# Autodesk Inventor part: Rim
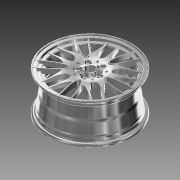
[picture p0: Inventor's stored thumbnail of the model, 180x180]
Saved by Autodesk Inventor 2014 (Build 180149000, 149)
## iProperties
Shininess: 64.0
Length Units: 11269
Angle Units: 11279
Time Units: 11290
Mass Units: 11283
Length Display Precision: 3
Angle Display Precision: 2
Compacted: True
Part Number: Rim
Document SubType Name: Modeling
Created: 2003-06
Manufacturer: Standard
Standards Organization: Custom
Density: 2.71 g/cm^3
Material: Aluminum-6061
Mass: 9934.83 g
Surface Area: 9000.12 cm^2
Volume: 3665.99 cm^3
Appearance: Chrome - Polished
Density: 0.0
Volumn: 0.0
Area: 0.0
PropertySet Name: Model Information
Control State: 0
Master: False
Checked Out: False
Author: Autodesk, Inc.
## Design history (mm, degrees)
workplane "Work Plane4"
workplane "Work Plane1"
sketch "Spoke Side"
  geometry: L1 (0, -11162.344)-(0, 13420.953) reference; L2 (-1298.767, 0)-(7792.602, 0) reference; L3 (0, 55)-(10.286, 55); L4 (205.698, 37.987)-(254.302, 42.013); L5 (37.4, 37.385)-(62.6, 42.615); L6 (0, 0)-(60, 0); L7 (60, 0)-(60, 5); L8 (60, 5)-(65.959, 10); L9 (62.17, 6.821)-(69.748, 13.179); L10 (222.425, 21.138)-(237.575, 18.862); L11 (230, 40)-(230, 20); L12 (0, 55)-(0, 0); A1 r 209.241 centre (212.724, 248.526) between (210.568, 39.297) and (249.283, 42.504); A2 r 109.305 centre (27.793, 147.025) between (39.866, 38.389) and (59.938, 42.554); A3 r 90.833 centre (0, -35.833) between (50, 40) and (0, 55); A4 r 10000 centre (6493.835, -7650.444) between (68.99, 12.543) and (68.985, 12.55); A5 r 10000 centre (1715.468, 9909.054) between (223.941, 20.912) and (236.06, 19.092); 2 further points
  constraints: 20 end point, 8 midpoint, 6 point on circle, 5 centre point, 2 collinear, 2 parallel, 2 point on line, 1 perpendicular, 1 tangent, 14 other
  dimensions: "d1" = 55 distance between parallel lines of L2 L3; "d3" = 460 diameter of L11.start L1; "d4" = 40 distance from line of L2 L11.start; "d5" = 100 diameter of A3.start L1; "d6" = 50 distance from line of L2 point (110.655, 50); "d7" = 40 distance from line of L2 A3.start; "d8" = 60 distance of L6.start L6.end; "d9" = 0 distance between parallel lines of L2 L6; "d10" = 5 distance of L6.end L7.end; "d11" = 460 diameter of L11.end L1 (= d3); "d12" = 130 deg angle of L7 L8; "d13" = 5 vertical distance of L7.end L8.end; "d14" = 20 distance of L11.start L11.end
revolve "Revolution1" stored, may be unused: angle "d15" = 90 deg
sketch "Spoke Top"
  geometry: L1 (0, 35.567)-(0, -35.567) reference; L2 (-329.417, 0)-(-41.965, 0) reference; A1 r 22.668 centre (-265.684, 0) between (-282.023, 15.713) and (-282.023, -15.713); 5 further points
  constraints: 3 symmetric about line, 2 point on circle, 1 centre point, 1 point on line, 7 other
  dimensions: "d137" = 85 distance from line of L1 point (-85, 0); "d138" = 30 distance of point (-95.703, -15) point (-95.703, 15); "d139" = 40 distance of point (-231.71, -20) point (-231.71, 20)
extrude "Extrusion9" cut sketch "Spoke Top" stored distance "d141" = 10; taper "d142" = -5 deg
pattern_circular "Circular Pattern6" dims angle "d145" = 360 deg
sketch "Sketch19"
  geometry: L1 (-50, 0)-(-86.059, 0) reference; L2 (-437.715, 0)-(341.286, 0) reference; L3 (0, 398.906)-(0, -364.894) reference; L4 (0, 0)-(-268.128, 194.806) reference; L5 (-101.443, 282.759)-(-96.692, 201.808); L6 (-221.81, 29.598)-(-300.268, 9.1); A1 r 230 centre (0, 0) between (196.304, -119.853) and (196.304, 119.853) reference; A2 r 230 centre (0, 0) between (174.648, 149.66) and (-53.325, 223.733) reference; A3 r 230 centre (0, 0) between (-88.366, 212.348) and (-229.261, 18.422) reference; A4 r 230 centre (0, 0) between (-229.261, -18.422) and (-88.366, -212.348) reference; A5 r 230 centre (0, 0) between (-53.325, -223.733) and (174.648, -149.66) reference; A6 r 130.796 centre (31.504, 249.946) between (-95.482, 281.288) and (-90.944, 203.966); A7 r 130.796 centre (-227.977, -107.2) between (-222.087, 23.464) and (-297.026, 3.886); A8 r 157.848 centre (-117.742, 85.544) between (-99.068, 242.284) and (-261.039, 19.349); 10 further points
  constraints: 6 end point, 4 midpoint, 4 point on circle, 3 centre point, 3 symmetric about line, 1 horizontal alignment, 1 point on line, 13 other
  dimensions: "d147" = 100 distance of A1.centre point (-80.902, 58.779); "d148" = 10 dimension on L6.start L6.end (= d149); "d149" = 10 dimension on L5.start L5.end
extrude "Extrusion10" cut sketch "Sketch19" stored distance "d150" = 10; taper "d151" = -5 deg
pattern_circular "Circular Pattern7" dims angle "d154" = 360 deg
sketch "Sketch20"
  geometry: L1 (-300.487, 0)-(50.081, 0) reference; L2 (0, 230.697)-(0, -38.449) reference; L3 (0, 0)-(-250.021, 181.651) reference; L4 (-230.266, 187.463)-(-204.629, 181.002); L5 (-235.377, 138.681)-(-249.444, 161.066); A1 r 50.044 centre (-229.678, 135.707) between (-205.46, 179.5) and (-230.246, 185.747); A2 r 50.044 centre (-200.039, 176.501) between (-247.806, 161.578) and (-234.205, 139.935); A3 r 27.755 centre (-215.47, 156.548) between (-217.447, 184.233) and (-242.411, 149.874); 5 further points
  constraints: 6 end point, 4 midpoint, 4 point on circle, 3 centre point, 3 point on line, 3 symmetric about line, 13 other
  dimensions: "d157" = 80 distance of L3.start point (-64.721, 47.023); "d158" = 285 distance of L3.start A3.start; "d159" = 5 dimension on L4.start L4.end; "d160" = 5 dimension on L5.start L5.end (= d159); "d161" = 22 distance of point (-76.988, 42.339) point (-64.057, 60.137)
extrude "Extrusion12" join sketch "Sketch20" distance "d164" = 40; taper "d165" = 5 deg
sketch "Sketch21" dims "d166" = 5
  geometry: L1 (0, 0)-(-271.586, 197.319); A1 r 27.755 centre (-215.47, 156.548) between (-217.447, 184.233) and (-242.411, 149.874) reference; 3 further points
  constraints: 2 end point, 2 point on line, 7 other
extrude "Extrusion13" cut sketch "Sketch21" stored distance "d167" = 20; taper "d168" = -1 deg
pattern_circular "Circular Pattern8" dims angle "d171" = 360 deg
sketch "Sketch22"
  geometry: L1 (60, 0)-(60, 5) reference; L2 (60, 5)-(65.959, 10) reference; L3 (60, 0)-(60, -25.42); L4 (60, -25.42)-(230, -25.42); L5 (230, -25.42)-(230, 20); L6 (0, 55)-(0, 0) reference
  constraints: 6 end point, 1 collinear, 1 parallel, 1 perpendicular
revolve "Revolution3" sketch "Sketch22" stored, may be unused: angle "d172" = 90 deg
sketch "Sketch23"
  geometry: C1 r 225 at (0, 0); C2 r 325 at (0, 0); 1 further point
  constraints: 2 centre point, 2 coincident
  dimensions: "d173" = 450 diameter of C1; "d174" = 650 diameter of C2
extrude "Extrusion14" cut sketch "Sketch23" stored distance "d175" = 20; taper "d176" = 0 deg
workplane "Work Plane5"
sketch "Sketch24"
  geometry: L1 (0, 202.622)-(0, -33.77) reference; L2 (-278.885, 0)-(46.481, 0) reference; L3 (0, 0)-(-232.404, 168.851) reference; C1 r 12.5 at (-36.406, 26.45); 4 further points
  constraints: 5 point on line, 2 end point, 1 centre point, 1 symmetric about line, 5 other
  dimensions: "d179" = 25 diameter of C1; "d180" = 45 distance of L3.start C1.centre; "d181" = 28 distance of L3.start point (-22.652, 16.458); "d182" = 70 distance of L3.start point (-56.631, 41.145); "d183" = 32 distance of point (-47.788, 14.943) point (-28.979, 40.832)
extrude "Extrusion15" cut sketch "Sketch24" distance "d184" = 40; taper "d185" = -3 deg
sketch "Sketch25"
  geometry: L1 (0, 318.17)-(0, -318.17) reference; L2 (-321.394, 0)-(321.205, 0) reference; L3 (0, 0)-(-199.929, 145.257); 2 further points
  constraints: 2 end point, 2 point on line, 1 midpoint
  dimensions: "d186" = 36 deg angle of L2 L3; "d187" = 45 distance of L3.start point (-36.406, 26.45)
hole "Hole2" sketch "Sketch25" at (-36.406, 26.45) diameter "d188" = 12; stored, may be unused: countersink angle "d192" = 82 deg, drill point angle "d194" = 118 deg; dims "d189" = 6, "d190" = 4, "d191" = 2, "d193" = 8
sketch "Sketch26"
  geometry: L1 (0, 10.5)-(0, -10.5) reference; L2 (-87, 0)-(14.5, 0) reference; C1 r 7.5 at (-65, 0); 1 further point
  constraints: 1 centre point, 1 point on line
  dimensions: "d195" = 65 distance from line of L1 C1.centre; "d196" = 15 diameter of C1
extrude "Extrusion16" cut sketch "Sketch26" distance "d197" = 40; taper "d198" = -3 deg
pattern_circular "Circular Pattern9" dims "d201" = 360 deg
sketch "Sketch27"
  geometry: C1 r 25 at (0, 0); 1 further point
  constraints: 1 centre point, 1 coincident
  dimensions: "d202" = 50 diameter of C1
extrude "Extrusion17" cut sketch "Sketch27" stored distance "d203" = 30; taper "d204" = -5 deg
chamfer "Chamfer3" distance "d205" = 2; stored, may be unused: second distance "d206" = 2, angle "d245" = 45 deg
fillet "Fillet9" dims "d210" = 5
fillet "Fillet10" dims "d211" = 2
fillet "Fillet11" dims "d212" = 1
fillet "Fillet12" dims "d244" = 5
sketch "Rim"
  geometry: L1 (0, -207.58)-(0, 101.58) reference; L2 (205.287, 15.102)-(198.66, 13.583); L3 (191.484, -47.284)-(187.573, 24.419); L4 (194.009, 7.408)-(197.061, -48.544); L5 (210.521, -135.213)-(211.543, -143.716); L6 (207.002, -147.832)-(197.328, -67.37); L7 (211.5, 28.893)-(211.5, 22.9); L8 (212.232, 37.523)-(211.523, 29.416); L9 (221, 43)-(218.209, 43); L10 (223, 52)-(223, 55); L11 (230, 55)-(230, 52); L12 (225, 57)-(228, 57); L13 (198.023, -53.072)-(200.538, -59.666); L14 (195.866, -61.447)-(192.767, -53.321); L15 (202.292, -66.774)-(208.594, -119.191); L16 (217.5, -149)-(221, -149); L17 (221, -156)-(215, -156); L18 (224, -161)-(224, -159); L19 (230, -158)-(230, -161); L20 (228, -163)-(226, -163); L21 (221, 50)-(209, 50); L22 (197, 37)-(192, 37); L23 (-722.944, 0)-(390.999, 0) reference; L24 (197, 37)-(205, 37); L25 (207, 39)-(207, 48); A1 r 752.499 centre (-563.809, -16.57) between (187.573, 24.419) and (187.133, 31.809); A2 r 8 centre (203.5, 22.9) between (205.287, 15.102) and (211.5, 22.9); A3 r 6 centre (200, 7.734) between (198.66, 13.583) and (194.009, 7.408); A4 r 6 centre (217.5, -143) between (211.543, -143.716) and (217.5, -149); A5 r 13.486 centre (223.91, -133.603) between (210.863, -130.19) and (210.521, -135.213); A6 r 9.5 centre (201.672, -127.786) between (210.863, -130.19) and (210.019, -123.25); A7 r 13.492 centre (221.874, -116.809) between (208.594, -119.191) and (210.019, -123.25); A8 r 6 centre (217.5, 28.893) between (211.523, 29.416) and (211.5, 28.893); A9 r 6 centre (218.209, 37) between (218.209, 43) and (212.232, 37.523); A10 r 2 centre (221, 52) between (221, 50) and (223, 52); A11 r 9 centre (221, 52) between (221, 43) and (230, 52); A12 r 2 centre (225, 55) between (225, 57) and (223, 55); A13 r 2 centre (228, 55) between (230, 55) and (228, 57); A14 r 15 centre (212.039, -47.727) between (197.061, -48.544) and (198.023, -53.072); A15 r 20 centre (211.455, -46.195) between (191.484, -47.284) and (192.767, -53.321); A16 r 30 centre (172.507, -70.355) between (202.292, -66.774) and (200.538, -59.666); A17 r 25 centre (172.507, -70.355) between (197.328, -67.37) and (195.866, -61.447); A18 r 8 centre (215, -148) between (207.002, -147.832) and (215, -156); A19 r 9 centre (221, -158) between (230, -158) and (221, -149); A20 r 3 centre (221, -159) between (224, -159) and (221, -156); A21 r 2 centre (226, -161) between (224, -161) and (226, -163); A22 r 2 centre (228, -161) between (228, -163) and (230, -161); A23 r 2 centre (209, 48) between (209, 50) and (207, 48); A24 r 4.877 centre (192, 32.123) between (192, 37) and (187.133, 31.809); A25 r 2 centre (205, 39) between (205, 37) and (207, 39); 4 further points
  constraints: 50 point on circle, 46 end point, 45 tangent, 25 centre point, 3 parallel, 1 perpendicular
  dimensions: "d266" = 2 radius of A23; "d267" = 220 distance between parallel lines of L20 L12; "d268" = 7 distance between parallel lines of L17 L16; "d269" = 5 distance between parallel lines of L6 L5; "d270" = 5 distance between parallel lines of L6 L15; "d271" = 5 distance between parallel lines of L14 L13; "d272" = 5.5 distance between parallel lines of L3 L4; "d273" = 50 distance between parallel lines of L23 L21; "d274" = 7 distance between parallel lines of L9 L21; "d276" = 8 radius of A2; "d277" = 9 radius of A11; "d278" = 2 radius of A13; "d279" = 2 radius of A12; "d280" = 2 radius of A10; "d282" = 6 radius of A3; "d283" = 15 radius of A14; "d284" = 20 radius of A15; "d285" = 30 radius of A16; "d286" = 25 radius of A17; "d287" = 9.5 radius of A6; "d288" = 6 radius of A4; "d289" = 9 radius of A19; "d290" = 2 radius of A22; "d291" = 2 radius of A21; "d292" = 3 radius of A20; "d293" = 8 radius of A18; "d294" = 57 distance between parallel lines of L23 L12; "d295" = 7 distance between parallel lines of L20 L17; "d296" = 460 diameter of L11 L1; "d298" = 460 diameter of L19 L1; "d299" = 18.5 distance between parallel lines of L7 L11; "d300" = 9 distance from line of A11.centre L11 (derived); "d301" = 21 distance from line of L11 A23.centre; "d304" = 38 distance from line of L11 A24.centre; "d305" = 30 distance from line of L11 A3.centre; "d306" = 7 distance between parallel lines of L11 L10; "d307" = 6 distance between parallel lines of L18 L19; "d308" = 9 distance from line of A19.centre L19 (derived); "d309" = 12.5 distance from line of A4.centre L19; "d310" = 15 distance from line of A18.centre L19; "d311" = 46.19501 distance from line of L23 A15.centre; "d312" = 47.72741 distance from line of L23 A14.centre; "d313" = 70.3547 distance from line of L23 A17.centre; "d314" = 77.49796 distance from line of L23 point (212.258, -77.498); "d332" = 20 distance between parallel lines of L12 L22; "d333" = 2 radius of A25
revolve "Revolution4" stored, may be unused: angle "d214" = 90 deg
sketch "Sketch33"
  geometry: L1 (208, 21)-(211, 21) reference; L2 (199, 8.5)-(199, 12) reference; L3 (185.213, 1.521)-(193.716, 2.543) reference; L4 (116.774, -6.708)-(169.191, -0.406) reference; L5 (103.072, -10.977)-(109.666, -8.462) reference; L6 (42.592, -14.991)-(98.544, -11.939) reference; L7 (34.898, -3.713)-(36.417, -10.34) reference; L8 (21.107, 2.5)-(27.1, 2.5) reference; L9 (12.477, 3.232)-(20.584, 2.523) reference; L10 (7, 12)-(7, 9.209) reference; L11 (-5, 21)-(-2, 21) reference; L12 (258.433, -209)-(-59.6, -209) reference; A1 r 9 centre (208, 12) between (208, 21) and (199, 12) reference; A2 r 6 centre (193, 8.5) between (193.716, 2.543) and (199, 8.5) reference; A3 r 13.486 centre (183.603, 14.91) between (180.19, 1.863) and (185.213, 1.521) reference; A4 r 9.5 centre (177.786, -7.328) between (180.19, 1.863) and (173.25, 1.019) reference; A5 r 13.492 centre (166.809, 12.874) between (169.191, -0.406) and (173.25, 1.019) reference; A6 r 30 centre (120.355, -36.493) between (116.774, -6.708) and (109.666, -8.462) reference; A7 r 15 centre (97.727, 3.039) between (98.544, -11.939) and (103.072, -10.977) reference; A8 r 6 centre (42.266, -9) between (36.417, -10.34) and (42.592, -14.991) reference; A9 r 8 centre (27.1, -5.5) between (34.898, -3.713) and (27.1, 2.5) reference; A10 r 6 centre (21.107, 8.5) between (20.584, 2.523) and (21.107, 2.5) reference; A11 r 6 centre (13, 9.209) between (7, 9.209) and (12.477, 3.232) reference; A12 r 9 centre (-2, 12) between (7, 12) and (-2, 21) reference
feature "RevolutionSrf1" sketch "Sketch33" dims angle "d315" = 90 deg
split "Split1"
pattern_circular "Circular Pattern11" dims angle "d317" = 360 deg
sketch "Sketch34"
  geometry: L1 (0, -399.846)-(0, 399.138) reference; L2 (-404.857, 0)-(355.966, 0) reference; L3 (0, 0)-(28.191, 10.261); L4 (0, 0)-(28.191, -10.261); L5 (28.191, 10.261)-(49.334, 17.956); L6 (28.191, -10.261)-(49.334, -17.956); C1 r 60 at (0, 0) reference; A1 r 52.5 centre (0, 0) between (49.334, 17.956) and (49.334, -17.956); A2 r 30 centre (0, 0) between (28.191, -10.261) and (28.191, 10.261); A3 r 52.5 centre (0, 0) between (52.5, 0) and (49.334, 17.956); A4 r 52.5 centre (0, 0) between (49.334, -17.956) and (52.5, 0); A5 r 30 centre (0, 0) between (0, -30) and (28.191, -10.261); A6 r 30 centre (0, 0) between (28.191, 10.261) and (0, -30)
  constraints: 12 point on circle, 8 end point, 6 centre point, 3 coincident, 3 point on line
  dimensions: "d319" = 40 deg angle of L4 L3; "d320" = 20 deg angle of L2 L3 (derived); "d321" = 105 diameter of A1; "d322" = 60 diameter of A2
extrude "Extrusion19" cut sketch "Sketch34" distance "d323" = 15; taper "d324" = -3 deg
fillet "Fillet18" dims "d325" = 2
chamfer "Chamfer5" distance "d326" = 2; stored, may be unused: second distance "d327" = 2, angle "d328" = 45 deg
pattern_circular "Circular Pattern12" dims "d330" = 360 deg
fillet "Fillet19" dims "d334" = 2
body "Solid1"
node "Projected Loop2"
body "Srf1"
other parameters: "d155" = 52
